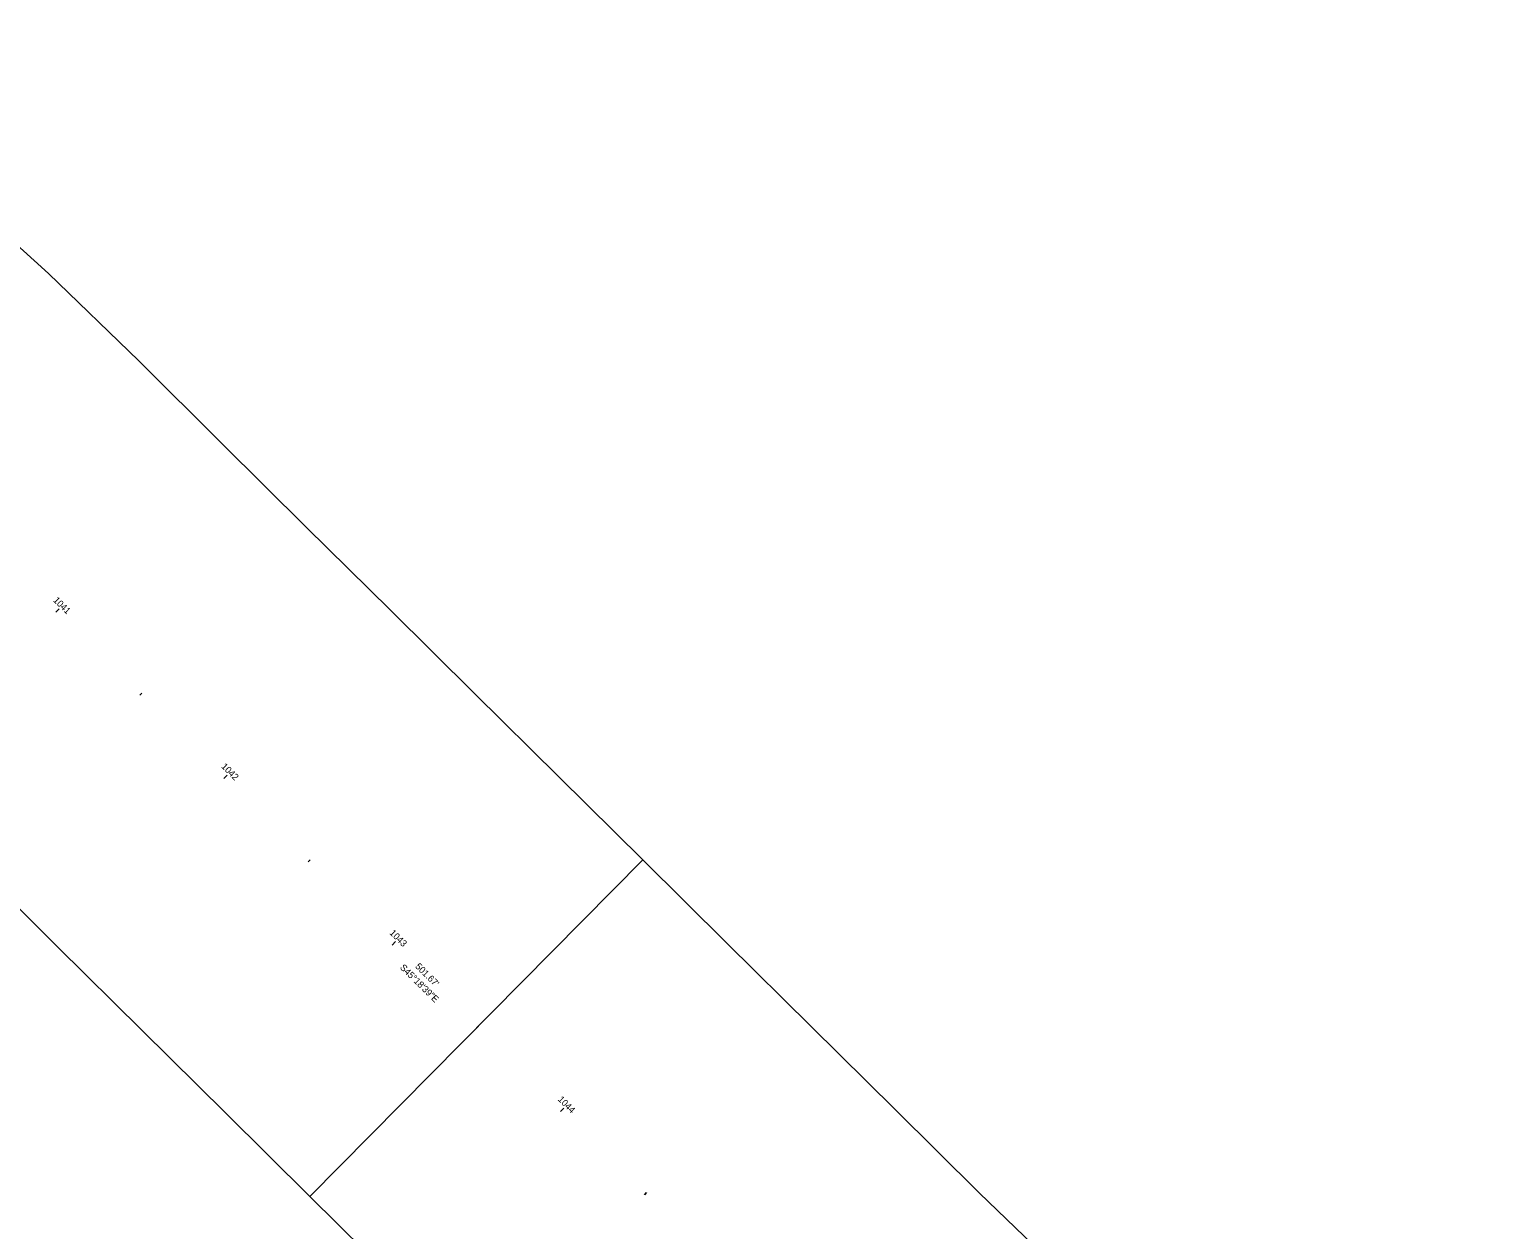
# Model space of a CAD drawing. Extents: x 1846275 to 1850613, y 577927 to 582526.
# Drawn here: x 1846912 to 1847529, y 581721 to 582229 of the extents above; entities that cross this region are included whole.
import ezdxf

# ---------------------------------------------------------------- set-up
doc = ezdxf.new("R2010")
doc.units = 0
for name, color, linetype in [('GE_P_Alignment_100_Cardinal_Points', 7, 'Continuous'), ('PM_P_Stop_Line', 7, 'Continuous'), ('SH_Named_Boundary', 7, 'Continuous'), ('XS_P_Pavt_Surface', 7, 'Continuous')]:
    doc.layers.add(name, color=color, linetype=linetype)

msp = doc.modelspace()

# ---------------------------------------------------------------- linework, layer by layer
at = {"layer": 'GE_P_Alignment_100_Cardinal_Points'}
for p, q in [((1846922.74, 581982.3), (1846924.15, 581983.73)), ((1846958.29, 581947.14), (1846959.13, 581947.99)), ((1846993.83, 581911.98), (1846995.24, 581913.4)), ((1847029.38, 581876.81), (1847030.23, 581877.67)), ((1847064.93, 581841.65), (1847066.33, 581843.07)), ((1847100.47, 581806.49), (1847101.32, 581807.34)), ((1847136.02, 581771.33), (1847137.43, 581772.75)), ((1847171.57, 581736.16), (1847172.41, 581737.02))]:
    msp.add_line(p, q, dxfattribs=at)
at = {"layer": 'SH_Named_Boundary'}
for points in [[(1846798.5, 582228.55), (1846675.89, 582070.54), (1846712.53, 582041.2), (1846748.25, 582010.76), (1846783.02, 581979.23), (1846816.81, 581946.65), (1846852.42, 581911.21), (1846887.96, 581876.05), (1846923.51, 581840.88), (1846959.06, 581805.72), (1846994.6, 581770.56), (1847030.15, 581735.39), (1847170.8, 581877.58), (1847135.26, 581912.74), (1847099.71, 581947.91), (1847064.16, 581983.07), (1847028.62, 582018.23), (1846993.07, 582053.39), (1846957.81, 582088.5), (1846919.61, 582125.33), (1846880.3, 582160.96), (1846839.91, 582195.38)], [(1847170.8, 581877.58), (1847030.15, 581735.39), (1847065.7, 581700.23), (1847101.24, 581665.07), (1847136.79, 581629.9), (1847172.34, 581594.74), (1847210.02, 581558.45), (1847246.38, 581524.12), (1847282.73, 581489.79), (1847319.08, 581455.46), (1847355.44, 581421.14), (1847391.79, 581386.81), (1847529.1, 581532.22), (1847492.75, 581566.55), (1847456.4, 581600.88), (1847420.04, 581635.21), (1847383.69, 581669.53), (1847347.34, 581703.86), (1847312.99, 581736.93), (1847277.44, 581772.09), (1847241.9, 581807.25), (1847206.35, 581842.42)]]:
    msp.add_lwpolyline(points, close=True, dxfattribs=at)

# ---------------------------------------------------------------- texts
at = {"layer": 'GE_P_Alignment_100_Cardinal_Points'}
for s, p in [('1041', (1846921.47, 581987.08)), ('1042', (1846992.47, 581916.85)), ('1043', (1847063.57, 581846.52)), ('1044', (1847134.66, 581776.19))]:
    msp.add_text(s, height=2.8, rotation=315.31074, dxfattribs=at).set_placement(p)
at = {"layer": 'PM_P_Stop_Line'}
msp.add_text('S45°18\'39"E', height=2.8, rotation=315.31074, dxfattribs=at).set_placement((1847067.98, 581831.88))
at = {"layer": 'XS_P_Pavt_Surface'}
msp.add_text("501.67'", height=2.8, rotation=315.31074, dxfattribs=at).set_placement((1847074.42, 581832.33))

doc.saveas('drawing.dxf')
